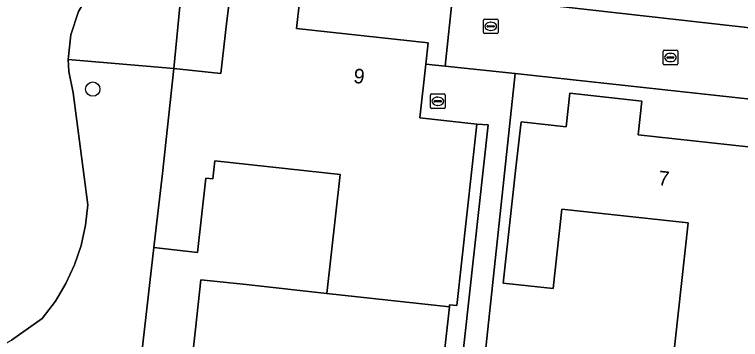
# Model space of a CAD drawing. Extents: x 162396 to 163643, y 386452 to 387406.
# Drawn here: x 162580.44 to 162630.14, y 386645.25 to 386667.51 of the extents above; entities that cross this region are included whole.
import ezdxf

# ---------------------------------------------------------------- set-up
doc = ezdxf.new("R2010")
doc.units = 0
for name, color, linetype in [('IMGEO_Boom', 7, 'Continuous'), ('IMGEO_Erf', 7, 'Continuous'), ('IMGEO_Groenvoorziening', 7, 'Continuous'), ('IMGEO_Kolk', 7, 'Continuous'), ('IMGEO_Pand', 7, 'Continuous'), ('IMGEO_Pand_nummerreeks', 7, 'Continuous'), ('IMGEO_Rijbaan_lokaal_open', 7, 'Continuous'), ('IMGEO_Rioolput', 7, 'Continuous'), ('IMGEO_Voetpad_open', 7, 'Continuous')]:
    doc.layers.add(name, color=color, linetype=linetype)

msp = doc.modelspace()

# ---------------------------------------------------------------- linework, layer by layer
at = {"layer": 'IMGEO_Boom'}
msp.add_circle((162585.797, 386662.4), 0.489, dxfattribs=at)
at = {"layer": 'IMGEO_Erf'}
for points in [[(162615.958, 386668.261), (162633.436, 386666.294), (162633.669, 386668.517), (162628.308, 386669.105), (162629.648, 386681.326), (162621.021, 386682.272), (162620.221, 386674.974), (162616.786, 386675.351)], [(162610.449, 386668.978), (162609.749, 386669.065), (162601.733, 386669.905), (162592.028, 386670.923), (162591.351, 386663.817), (162594.573, 386663.463), (162594.971, 386667.081), (162595.168, 386668.713), (162599.619, 386668.21), (162599.642, 386668.409), (162599.94, 386668.376), (162599.735, 386666.557), (162608.75, 386665.564), (162608.59, 386664.114), (162609.92, 386663.966)], [(162633.187, 386658.247), (162633.536, 386661.425), (162614.719, 386663.466), (162610.524, 386624.181), (162628.73, 386617.707)]]:
    msp.add_lwpolyline(points, close=True, dxfattribs=at)
for points in [[(162625.201, 386640.975), (162626.551, 386653.238), (162617.912, 386654.19), (162617.313, 386648.746), (162613.898, 386649.122), (162614.767, 386657.009), (162615.115, 386660.168), (162618.205, 386659.827), (162618.457, 386662.113), (162623.397, 386661.568), (162623.144, 386659.279), (162631.91, 386658.314)], [(162608.983, 386624.745), (162612.855, 386659.948), (162612.099, 386659.995), (162610.731, 386647.58), (162610.224, 386647.635), (162610.208, 386647.493), (162609.67, 386642.605)], [(162592.041, 386638.819), (162592.828, 386645.969), (162593.2, 386649.351), (162596.304, 386649.01), (162601.831, 386648.402), (162602.729, 386656.552), (162594.151, 386657.498), (162594.014, 386656.252), (162593.528, 386656.305), (162592.958, 386651.21), (162589.976, 386651.544), (162587.764, 386632.176)]]:
    msp.add_lwpolyline(points, dxfattribs=at)
at = {"layer": 'IMGEO_Groenvoorziening'}
for points in [[(162584.448, 386662.137), (162584.159, 386663.601), (162584.117, 386664.44), (162584.297, 386666.11), (162584.82, 386667.705), (162585.664, 386669.157), (162587.003, 386670.859), (162588.62, 386672.535), (162590.404, 386674.032), (162590.907, 386674.421), (162591.332, 386674.478), (162591.645, 386674.404), (162591.999, 386674.162), (162592.182, 386673.897), (162592.283, 386673.481), (162592.242, 386673.162), (162592.028, 386670.923), (162601.733, 386669.905), (162606.26, 386676.648), (162588.055, 386683.142)], [(162585.251, 386682.32), (162552.759, 386647.097), (162553.905, 386647.412), (162554.758, 386647.536), (162555.62, 386647.57), (162557.329, 386647.367), (162562.706, 386645.266), (162565.417, 386644.265), (162568.605, 386643.432), (162571.863, 386642.938), (162575.154, 386642.786), (162577.994, 386643.962), (162580.239, 386645.21), (162582.341, 386646.687), (162583.233, 386647.877), (162583.952, 386649.088), (162584.54, 386650.368), (162584.991, 386651.702), (162585.3, 386653.076), (162585.464, 386654.475), (162584.448, 386662.137)], [(162550.979, 386645.25), (162587.764, 386632.176), (162589.976, 386651.544), (162590.56, 386656.632), (162591.351, 386663.817), (162584.117, 386664.44), (162584.159, 386663.601), (162584.448, 386662.137), (162585.464, 386654.475), (162585.3, 386653.076), (162584.991, 386651.702), (162584.54, 386650.368), (162583.952, 386649.088), (162583.233, 386647.877), (162582.341, 386646.687), (162580.239, 386645.21)]]:
    msp.add_lwpolyline(points, dxfattribs=at)
msp.add_lwpolyline([(162591.351, 386663.817), (162592.028, 386670.923), (162592.242, 386673.162), (162592.283, 386673.481), (162592.182, 386673.897), (162591.999, 386674.162), (162591.645, 386674.404), (162591.332, 386674.478), (162590.907, 386674.421), (162590.404, 386674.032), (162588.62, 386672.535), (162587.003, 386670.859), (162585.664, 386669.157), (162584.82, 386667.705), (162584.297, 386666.11), (162584.117, 386664.44)], close=True, dxfattribs=at)
at = {"layer": 'IMGEO_Kolk'}
for p, q in [((162612.618, 386667.2), (162613.47, 386667.2)), ((162612.543, 386666.274), (162612.543, 386667.126)), ((162612.802, 386666.694), (162612.802, 386666.706)), ((162612.845, 386666.743), (162613.243, 386666.743)), ((162613.031, 386666.98), (162613.056, 386666.98)), ((162613.286, 386666.706), (162613.286, 386666.694)), ((162613.544, 386667.126), (162613.544, 386666.274)), ((162613.24, 386666.657), (162612.842, 386666.657)), ((162613.054, 386666.42), (162613.029, 386666.42)), ((162613.47, 386666.2), (162612.618, 386666.2)), ((162624.844, 386664.14), (162624.844, 386664.992)), ((162624.919, 386665.066), (162625.771, 386665.066)), ((162625.332, 386664.846), (162625.357, 386664.846)), ((162625.845, 386664.992), (162625.845, 386664.14)), ((162625.103, 386664.56), (162625.103, 386664.572)), ((162625.541, 386664.523), (162625.143, 386664.523)), ((162625.146, 386664.609), (162625.544, 386664.609)), ((162625.355, 386664.286), (162625.33, 386664.286)), ((162625.587, 386664.572), (162625.587, 386664.56)), ((162625.771, 386664.066), (162624.919, 386664.066))]:
    msp.add_line(p, q, dxfattribs=at)
for points in [[(162612.618, 386667.2), (162613.47, 386667.2)], [(162612.543, 386666.274), (162612.543, 386667.126)], [(162613.544, 386667.126), (162613.544, 386666.274)], [(162613.47, 386666.2), (162612.618, 386666.2)], [(162624.844, 386664.14), (162624.844, 386664.992)], [(162624.919, 386665.066), (162625.771, 386665.066)], [(162625.845, 386664.992), (162625.845, 386664.14)], [(162625.771, 386664.066), (162624.919, 386664.066)]]:
    msp.add_lwpolyline(points, dxfattribs=at)
for centre, radius, start, end in [((162612.62, 386667.124), 0.0765, 91.552, 178.448), ((162612.62, 386667.124), 0.0765, 91.552, 178.448), ((162613.468, 386667.124), 0.0765, 1.552, 88.448), ((162613.468, 386667.124), 0.0765, 1.552, 88.448), ((162612.842, 386666.703), 0.0403, 85.8775, 175.7526), ((162613.247, 386666.705), 0.0386, 1.7309, 96.639), ((162612.62, 386666.276), 0.0765, 181.552, 268.448), ((162612.62, 386666.276), 0.0765, 181.552, 268.448), ((162612.839, 386666.693), 0.0366, 178.938, 274.7102), ((162613.243, 386666.7), 0.043, 264.8664, 352.4533), ((162613.468, 386666.276), 0.0765, 271.552, 358.448), ((162613.468, 386666.276), 0.0765, 271.552, 358.448), ((162624.921, 386664.99), 0.0765, 91.552, 178.448), ((162624.921, 386664.99), 0.0765, 91.552, 178.448), ((162625.769, 386664.99), 0.0765, 1.552, 88.448), ((162625.769, 386664.99), 0.0765, 1.552, 88.448), ((162625.143, 386664.569), 0.0403, 85.8775, 175.7526), ((162625.14, 386664.559), 0.0366, 178.938, 274.7102), ((162625.544, 386664.566), 0.043, 264.8664, 352.4533), ((162625.548, 386664.571), 0.0386, 1.7309, 96.639), ((162624.921, 386664.142), 0.0765, 181.552, 268.448), ((162624.921, 386664.142), 0.0765, 181.552, 268.448), ((162625.769, 386664.142), 0.0765, 271.552, 358.448), ((162625.769, 386664.142), 0.0765, 271.552, 358.448)]:
    msp.add_arc(centre, radius, start, end, dxfattribs=at)
for centre, major_axis, ratio, start_param, end_param in [((162613.03, 386666.7), (-0.387, 0.002), 0.722429, 4.712389, 7.853982), ((162613.055, 386666.7), (-0.39, 0.002), 0.717154, 1.570796, 4.712389), ((162625.331, 386664.566), (-0.387, 0.002), 0.722429, 4.712389, 7.853982), ((162625.356, 386664.566), (-0.39, 0.002), 0.717154, 1.570796, 4.712389)]:
    msp.add_ellipse(centre, major_axis=major_axis, ratio=ratio, start_param=start_param, end_param=end_param, dxfattribs=at)
at = {"layer": 'IMGEO_Pand'}
for points in [[(162589.976, 386651.544), (162592.958, 386651.21), (162593.528, 386656.305), (162594.014, 386656.252), (162594.151, 386657.498), (162602.729, 386656.552), (162601.831, 386648.402), (162610.208, 386647.493), (162610.224, 386647.635), (162610.731, 386647.58), (162612.099, 386659.995), (162608.185, 386660.426), (162608.59, 386664.114), (162608.75, 386665.564), (162599.735, 386666.557), (162599.94, 386668.376), (162599.642, 386668.409), (162599.619, 386668.21), (162595.168, 386668.713), (162594.971, 386667.081), (162594.573, 386663.463), (162591.351, 386663.817), (162590.56, 386656.632)], [(162631.91, 386658.314), (162623.144, 386659.279), (162623.397, 386661.568), (162618.457, 386662.113), (162618.205, 386659.827), (162615.115, 386660.168), (162614.767, 386657.009), (162613.898, 386649.122), (162617.313, 386648.746), (162617.912, 386654.19), (162626.551, 386653.238), (162625.201, 386640.975), (162630.059, 386640.442), (162630.508, 386640.393), (162631.867, 386652.737), (162631.302, 386652.8)], [(162596.304, 386649.01), (162593.2, 386649.351), (162592.828, 386645.969), (162592.041, 386638.819), (162595.395, 386638.449), (162595.981, 386643.772), (162604.668, 386642.815), (162603.325, 386630.619), (162608.688, 386630.029), (162610.068, 386642.562), (162609.67, 386642.605), (162610.208, 386647.493), (162601.831, 386648.402)]]:
    msp.add_lwpolyline(points, close=True, dxfattribs=at)
at = {"layer": 'IMGEO_Rijbaan_lokaal_open'}
for points in [[(162727.566, 386670.164), (162708.666, 386672.324), (162708.493, 386672.348), (162708.151, 386672.418), (162707.816, 386672.519), (162696.344, 386676.37), (162678.572, 386678.387), (162676.339, 386678.636), (162675.851, 386674.18), (162658.039, 386676.168), (162655.154, 386676.489), (162654.796, 386673.146), (162654.582, 386671.122), (162637.224, 386673.17), (162634.219, 386673.532), (162633.669, 386668.517), (162633.436, 386666.294), (162615.958, 386668.261), (162616.786, 386675.351), (162617, 386677.306), (162613.339, 386677.648)], [(162610.449, 386668.978), (162609.92, 386663.966), (162614.719, 386663.466), (162633.536, 386661.425), (162633.187, 386658.247), (162628.73, 386617.707), (162630.221, 386617.233), (162634.64, 386658.079), (162653.657, 386655.937), (162654.99, 386655.608), (162658.928, 386655.156), (162659.28, 386658.465), (162674.242, 386656.758), (162675.871, 386656.617), (162679.639, 386656.195), (162679.727, 386656.879), (162679.981, 386658.864), (162694.884, 386657.146), (162696.053, 386656.935), (162700.284, 386656.459), (162701.024, 386662.577), (162701.576, 386668.308), (162725.964, 386665.516)]]:
    msp.add_lwpolyline(points, dxfattribs=at)
at = {"layer": 'IMGEO_Rioolput'}
for p, q in [((162608.917, 386661.142), (162608.917, 386661.994)), ((162608.992, 386662.068), (162609.844, 386662.068)), ((162609.405, 386661.848), (162609.43, 386661.848)), ((162609.918, 386661.994), (162609.918, 386661.142)), ((162609.176, 386661.562), (162609.176, 386661.574)), ((162609.614, 386661.525), (162609.216, 386661.525)), ((162609.219, 386661.611), (162609.617, 386661.611)), ((162609.428, 386661.288), (162609.403, 386661.288)), ((162609.66, 386661.574), (162609.66, 386661.562)), ((162609.844, 386661.068), (162608.992, 386661.068))]:
    msp.add_line(p, q, dxfattribs=at)
for points in [[(162608.917, 386661.142), (162608.917, 386661.994)], [(162608.992, 386662.068), (162609.844, 386662.068)], [(162609.918, 386661.994), (162609.918, 386661.142)], [(162609.844, 386661.068), (162608.992, 386661.068)]]:
    msp.add_lwpolyline(points, dxfattribs=at)
for centre, radius, start, end in [((162608.994, 386661.992), 0.0765, 91.552, 178.448), ((162608.994, 386661.992), 0.0765, 91.552, 178.448), ((162609.842, 386661.992), 0.0765, 1.552, 88.448), ((162609.842, 386661.992), 0.0765, 1.552, 88.448), ((162609.216, 386661.571), 0.0403, 85.8775, 175.7526), ((162609.213, 386661.561), 0.0366, 178.938, 274.7102), ((162609.617, 386661.568), 0.043, 264.8664, 352.4533), ((162609.621, 386661.573), 0.0386, 1.7309, 96.639), ((162608.994, 386661.144), 0.0765, 181.552, 268.448), ((162608.994, 386661.144), 0.0765, 181.552, 268.448), ((162609.842, 386661.144), 0.0765, 271.552, 358.448), ((162609.842, 386661.144), 0.0765, 271.552, 358.448)]:
    msp.add_arc(centre, radius, start, end, dxfattribs=at)
for centre, major_axis, ratio, start_param, end_param in [((162609.404, 386661.568), (-0.387, 0.002), 0.722429, 4.712389, 7.853982), ((162609.429, 386661.568), (-0.39, 0.002), 0.717154, 1.570796, 4.712389)]:
    msp.add_ellipse(centre, major_axis=major_axis, ratio=ratio, start_param=start_param, end_param=end_param, dxfattribs=at)
at = {"layer": 'IMGEO_Voetpad_open'}
msp.add_lwpolyline([(162609.92, 386663.966), (162608.59, 386664.114), (162608.185, 386660.426), (162612.099, 386659.995), (162612.855, 386659.948), (162608.983, 386624.745), (162610.524, 386624.181), (162614.719, 386663.466)], close=True, dxfattribs=at)

# ---------------------------------------------------------------- texts
at = {"layer": 'IMGEO_Pand_nummerreeks'}
for s, rotation, p in [('9', 353.7142, (162603.609, 386662.831)), ('7', 353.7147, (162624.471, 386655.833))]:
    msp.add_text(s, height=1, rotation=rotation, dxfattribs=at).set_placement(p)

doc.saveas('drawing.dxf')
